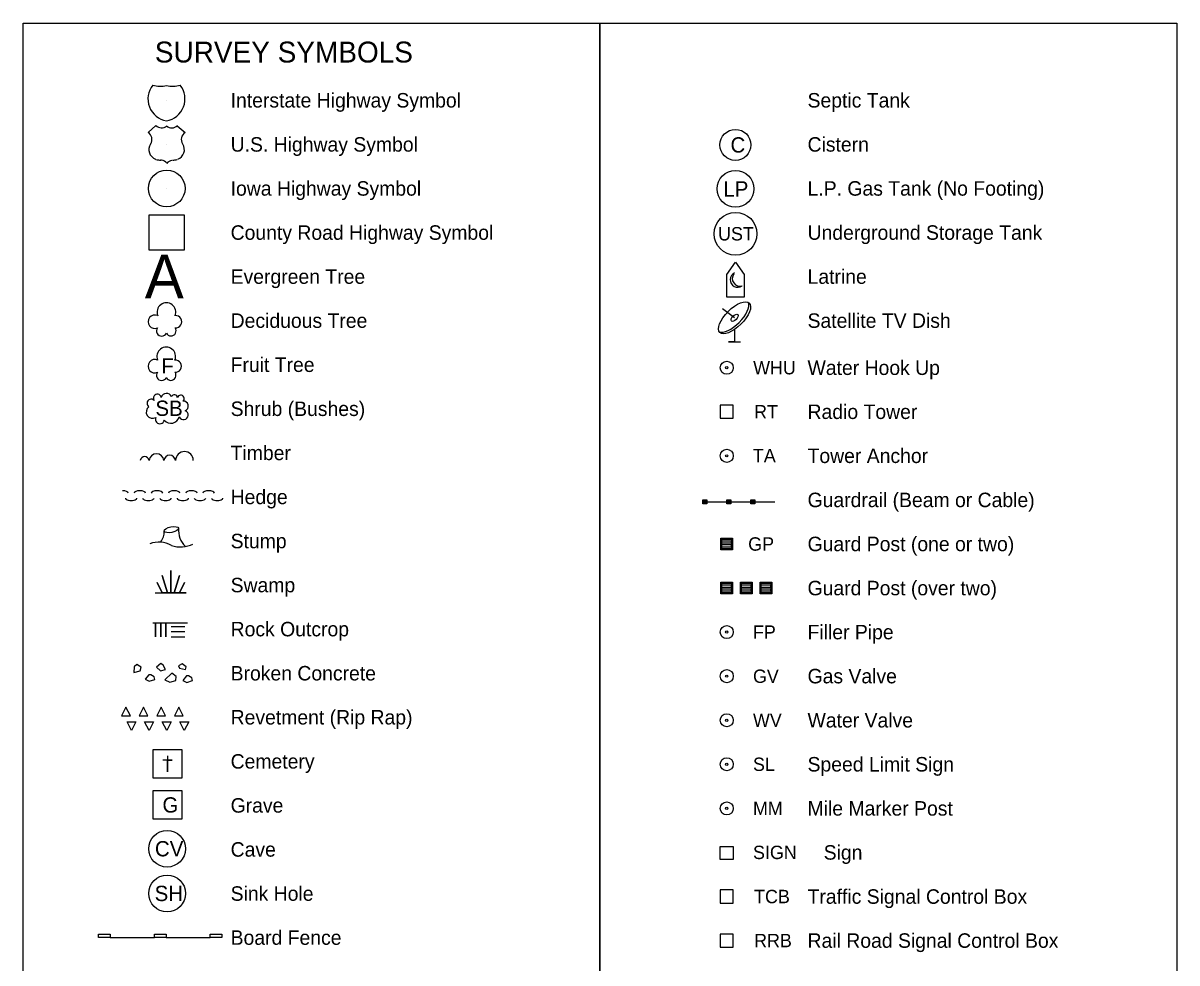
# Model space of a CAD drawing. Extents: x 6082259 to 6083454, y 5964102 to 5966092.
# Drawn here: x 6082259 to 6083454, y 5965119 to 5966092 of the extents above; entities that cross this region are included whole.
import ezdxf

# ---------------------------------------------------------------- set-up
doc = ezdxf.new("R2010")
doc.units = 0
for name, color, linetype in [('Default', 7, 'Continuous'), ('dsnTextShtTitle', 7, 'Continuous'), ('ShtPlotIdentification', 7, 'Continuous')]:
    doc.layers.add(name, color=color, linetype=linetype)

msp = doc.modelspace()

# ---------------------------------------------------------------- linework, layer by layer
at = {"layer": 'Default'}
for points in [[(6082259, 5966092.2), (6082856.5, 5966092.2), (6082856.5, 5964102.2), (6082259, 5964102.2)], [(6082856.5, 5966092.2), (6083454, 5966092.2), (6083454, 5964102.2), (6082856.5, 5964102.2)]]:
    msp.add_lwpolyline(points, close=True, dxfattribs=at)
at = {"layer": 'ShtPlotIdentification'}
for p, q in [((6082407.8, 5966012.2), (6082407.8, 5966012.2)), ((6082388.5, 5965978.8), (6082396.6, 5965986)), ((6082418.8, 5965985.9), (6082426.9, 5965978.7)), ((6082391, 5965966.7), (6082391.4, 5965967.3)), ((6082407.8, 5965966.5), (6082407.8, 5965966.5)), ((6082396.7, 5965951), (6082396, 5965951.3)), ((6082402.5, 5965950.1), (6082401.5, 5965950.1)), ((6082407.8, 5965920.9), (6082407.8, 5965920.9)), ((6082995.9, 5965786.9), (6082983.5, 5965796.2)), ((6082412.3, 5965467.3), (6082426.5, 5965467.3)), ((6082412.3, 5965462), (6082426.5, 5965462)), ((6082412.3, 5965456.6), (6082426.5, 5965456.6))]:
    msp.add_line(p, q, dxfattribs=at)
for points in [[(6082389.5, 5965893.5), (6082426, 5965893.5), (6082426, 5965857), (6082389.5, 5965857), (6082389.5, 5965893.5)], [(6082987.8, 5965808.3), (6082987.8, 5965831.8), (6082996.9, 5965844.5), (6083005.9, 5965831.8), (6083005.9, 5965808.3), (6082987.8, 5965808.3)], [(6082995.9, 5965774.5), (6082995.9, 5965762.1), (6082989.7, 5965762.1), (6083002.1, 5965762.1)], [(6082987.8, 5965682.8), (6082987.8, 5965682.8), (6082994.6, 5965682.8), (6082994.6, 5965696.4), (6082981, 5965696.4), (6082981, 5965682.8), (6082987.8, 5965682.8)], [(6082963.2, 5965594.3), (6082963.2, 5965598.4), (6082967.3, 5965598.4), (6082967.3, 5965594.3), (6082963.2, 5965594.3), (6082963.2, 5965595.7), (6082967.3, 5965595.7), (6082967.3, 5965597), (6082963.2, 5965597)], [(6082963.2, 5965596.4), (6083037.5, 5965596.4)], [(6082988, 5965594.3), (6082988, 5965598.4), (6082992.1, 5965598.4), (6082992.1, 5965594.3), (6082988, 5965594.3), (6082988, 5965595.7), (6082992.1, 5965595.7), (6082992.1, 5965597), (6082988, 5965597)], [(6083012.7, 5965594.3), (6083012.7, 5965598.4), (6083016.9, 5965598.4), (6083016.9, 5965594.3), (6083012.7, 5965594.3), (6083012.7, 5965595.7), (6083016.9, 5965595.7), (6083016.9, 5965597), (6083012.7, 5965597)], [(6082982.8, 5965547.7), (6082982.8, 5965557.6), (6082992.7, 5965557.6), (6082992.7, 5965547.7), (6082982.8, 5965547.7), (6082982.8, 5965549.7), (6082992.7, 5965549.7), (6082992.7, 5965551.7), (6082982.8, 5965551.7), (6082982.8, 5965553.7), (6082992.7, 5965553.7), (6082992.7, 5965555.6), (6082982.8, 5965555.6)], [(6082396, 5965502.1), (6082428.1, 5965502.1), (6082421, 5965502.1), (6082426.3, 5965512.8), (6082421, 5965502.1), (6082415.6, 5965502.1), (6082421, 5965520), (6082415.6, 5965502.1), (6082412.1, 5965502.1), (6082412.1, 5965525.3), (6082412.1, 5965502.1), (6082408.5, 5965502.1), (6082403.2, 5965520), (6082408.5, 5965502.1), (6082403.2, 5965502.1), (6082397.8, 5965512.8), (6082403.2, 5965502.1)], [(6082982.8, 5965502.1), (6082982.8, 5965512), (6082992.7, 5965512), (6082992.7, 5965502.1), (6082982.8, 5965502.1), (6082982.8, 5965504.1), (6082992.7, 5965504.1), (6082992.7, 5965506), (6082982.8, 5965506), (6082982.8, 5965508), (6082992.7, 5965508), (6082992.7, 5965510), (6082982.8, 5965510)], [(6083003.2, 5965502.1), (6083003.2, 5965512), (6083013.1, 5965512), (6083013.1, 5965502.1), (6083003.2, 5965502.1), (6083003.2, 5965504.1), (6083013.1, 5965504.1), (6083013.1, 5965506), (6083003.2, 5965506), (6083003.2, 5965508), (6083013.1, 5965508), (6083013.1, 5965510), (6083003.2, 5965510)], [(6083023.5, 5965502.1), (6083023.5, 5965512), (6083033.4, 5965512), (6083033.4, 5965502.1), (6083023.5, 5965502.1), (6083023.5, 5965504.1), (6083033.4, 5965504.1), (6083033.4, 5965506), (6083023.5, 5965506), (6083023.5, 5965508), (6083033.4, 5965508), (6083033.4, 5965510), (6083023.5, 5965510)], [(6082393.5, 5965470.9), (6082396.2, 5965470.9), (6082396.2, 5965456.6), (6082396.2, 5965470.9), (6082401.6, 5965470.9), (6082401.6, 5965456.6), (6082401.6, 5965470.9), (6082406.9, 5965470.9), (6082406.9, 5965456.6), (6082406.9, 5965470.9), (6082429.2, 5965470.9)], [(6082361, 5965374.6), (6082370.2, 5965374.6), (6082365.6, 5965383.8), (6082361, 5965374.6)], [(6082379.3, 5965374.6), (6082388.4, 5965374.6), (6082383.9, 5965383.8), (6082379.3, 5965374.6)], [(6082397.6, 5965374.6), (6082406.7, 5965374.6), (6082402.1, 5965383.8), (6082397.6, 5965374.6)], [(6082415.8, 5965374.6), (6082424.9, 5965374.6), (6082420.4, 5965383.8), (6082415.8, 5965374.6)], [(6082366.7, 5965368.6), (6082375.8, 5965368.6), (6082371.2, 5965359.5), (6082366.7, 5965368.6)], [(6082384.9, 5965368.6), (6082394.1, 5965368.6), (6082389.5, 5965359.5), (6082384.9, 5965368.6)], [(6082403.2, 5965368.6), (6082412.3, 5965368.6), (6082407.8, 5965359.5), (6082403.2, 5965368.6)], [(6082421.5, 5965368.6), (6082430.6, 5965368.6), (6082426, 5965359.5), (6082421.5, 5965368.6)], [(6082393.8, 5965310.2), (6082393.8, 5965339.7), (6082423.4, 5965339.7), (6082423.4, 5965310.2), (6082393.8, 5965310.2)], [(6082408.6, 5965333.3), (6082408.6, 5965316.6), (6082408.6, 5965328.9), (6082413.5, 5965328.9), (6082403.7, 5965328.9)], [(6082987.8, 5965180.8), (6082987.8, 5965180.8), (6082994.6, 5965180.8), (6082994.6, 5965194.3), (6082981, 5965194.3), (6082981, 5965180.8), (6082987.8, 5965180.8)], [(6082349.4, 5965145), (6082395, 5965145)], [(6082407.2, 5965145), (6082452.8, 5965145)], [(6082464.9, 5965145), (6082464.9, 5965145)], [(6082987.8, 5965135.1), (6082987.8, 5965135.1), (6082994.6, 5965135.1), (6082994.6, 5965148.7), (6082981, 5965148.7), (6082981, 5965135.1), (6082987.8, 5965135.1)]]:
    msp.add_lwpolyline(points, dxfattribs=at)
for points in [[(6082981.8, 5965546.7), (6082981.8, 5965558.6), (6082993.7, 5965558.6), (6082993.7, 5965546.7)], [(6082981.8, 5965501.1), (6082981.8, 5965513), (6082993.7, 5965513), (6082993.7, 5965501.1)], [(6083002.2, 5965501.1), (6083002.2, 5965513), (6083014.1, 5965513), (6083014.1, 5965501.1)], [(6083022.5, 5965501.1), (6083022.5, 5965513), (6083034.4, 5965513), (6083034.4, 5965501.1)], [(6082401.7, 5965429), (6082397.3, 5965424.9), (6082401.5, 5965421.3), (6082406.4, 5965422.8), (6082404.3, 5965427.2)], [(6082423.7, 5965428.6), (6082419.9, 5965426.3), (6082421.1, 5965424.2), (6082427.1, 5965422.6), (6082427.9, 5965425.5)], [(6082376.8, 5965427.8), (6082374.2, 5965425.4), (6082373.7, 5965419.7), (6082380.2, 5965421.3), (6082381.5, 5965424.9), (6082379.7, 5965426.2)], [(6082389.2, 5965417.2), (6082385.6, 5965412.5), (6082389.8, 5965410.4), (6082395.5, 5965412.3), (6082394.9, 5965415.1), (6082391.3, 5965417.2)], [(6082413.2, 5965419), (6082406, 5965411.8), (6082410.9, 5965409.4), (6082417.4, 5965411.3), (6082417.6, 5965415.4)], [(6082428.2, 5965416), (6082424.6, 5965411.4), (6082428.7, 5965409.3), (6082434.4, 5965411.1), (6082433.9, 5965413.9), (6082430.3, 5965416)], [(6082393.7, 5965267.5), (6082393.7, 5965297.2), (6082423.5, 5965297.2), (6082423.5, 5965267.5)], [(6082981, 5965225.7), (6082981, 5965239.2), (6082994.6, 5965239.2), (6082994.6, 5965225.7)], [(6082337.2, 5965145), (6082337.2, 5965148.4), (6082349.4, 5965148.4), (6082349.4, 5965145)], [(6082395, 5965145), (6082395, 5965148.4), (6082407.2, 5965148.4), (6082407.2, 5965145)], [(6082452.8, 5965145), (6082452.8, 5965148.4), (6082464.9, 5965148.4), (6082464.9, 5965145)]]:
    msp.add_lwpolyline(points, close=True, dxfattribs=at)
for centre, radius in [((6082996.8, 5965966), 16), ((6082407.8, 5965920.9), 19), ((6082996.9, 5965920.5), 19), ((6082996.9, 5965873.9), 22.2), ((6082987.8, 5965735.2), 6.79), ((6082987.8, 5965735.2), 1.13), ((6082987.8, 5965644), 6.79), ((6082987.8, 5965644), 1.13), ((6082987.8, 5965461.4), 6.79), ((6082987.8, 5965461.4), 1.13), ((6082987.8, 5965415.8), 6.79), ((6082987.8, 5965415.8), 1.13), ((6082987.8, 5965370.1), 6.79), ((6082987.8, 5965370.1), 1.13), ((6082987.8, 5965324.5), 6.79), ((6082987.8, 5965324.5), 1.13), ((6082987.8, 5965278.8), 6.79), ((6082987.8, 5965278.8), 1.13), ((6082408.2, 5965237), 19), ((6082408.2, 5965190.7), 19)]:
    msp.add_circle(centre, radius, dxfattribs=at)
for centre, radius, start, end in [((6082411.4, 5966013.6), 23, 141.2897, 260.377), ((6082401.1, 5966050), 23.3, 250.8344, 286.0898), ((6082414, 5966050), 23.3, 253.9102, 289.1613), ((6082403.7, 5966013.6), 23, 279.623, 38.7204), ((6082414, 5966050), 23.3, 289.1818, 289.185), ((6082384.1, 5965971.6), 8.46, 328.1178, 58.4185), ((6082402.4, 5965992.1), 8.46, 226.652, 308.6604), ((6082413, 5965992.1), 8.46, 230.5703, 313.348), ((6082431.3, 5965971.5), 8.46, 121.5815, 211.8822), ((6082399.6, 5965961), 10.3, 145.8972, 250.3585), ((6082415.8, 5965960.9), 10.3, 289.6415, 34.1028), ((6082403.5, 5965974.1), 24.1, 253.4797, 265.7777), ((6082402.1, 5965943), 7.07, 33.6844, 87.4407), ((6082413.9, 5965942.9), 7.07, 95.8567, 146.3156), ((6082411.9, 5965974.1), 24.1, 274.6642, 286.5203), ((6082999.3, 5965826.4), 7.87, 116.2289, 304.7925), ((6083001.5, 5965827.5), 7.91, 142.8907, 286.2253), ((6082407.5, 5965792.7), 9.75, 338.2051, 201.7949), ((6082395.5, 5965782.8), 6.97, 65.4824, 294.5175), ((6082417, 5965782.8), 6.36, 265.9982, 94.0018), ((6082402.6, 5965773.2), 5.31, 142.7501, 335.3223), ((6082412.2, 5965773.4), 5.3, 206.5242, 35.4033), ((6082407.3, 5965746.8), 9.75, 338.2051, 201.7949), ((6082395.4, 5965736.8), 6.97, 65.4824, 294.5175), ((6082416.8, 5965736.8), 6.36, 265.9982, 94.0018), ((6082402.5, 5965727.3), 5.31, 142.7501, 335.3223), ((6082412.1, 5965727.4), 5.3, 206.5242, 35.4033), ((6082398.1, 5965703.7), 4.12, 10.5948, 214.3611), ((6082407.6, 5965703.1), 5.57, 22.6036, 165.7836), ((6082415.7, 5965704.1), 3.15, 0.4605, 158.7839), ((6082422.3, 5965703.3), 3.57, 311.3936, 166.4114), ((6082393.2, 5965689.4), 6.62, 125.8289, 299.2848), ((6082391.7, 5965698.3), 4.32, 45.3455, 236.8073), ((6082425, 5965695.5), 5.15, 290.9039, 94.3687), ((6082400.8, 5965681.8), 4.68, 157.0258, 349.7602), ((6082412.2, 5965686.7), 8.99, 220.0183, 343.6977), ((6082425.2, 5965686.2), 4.79, 204.8294, 69.8871), ((6082397.2, 5965638.4), 7.66, 5.6097, 174.3903), ((6082410.9, 5965638.4), 6.15, 6.8184, 173.1816), ((6082426.2, 5965639.2), 9.15, 0, 180), ((6082385, 5965638.5), 4.63, 8.8069, 171.1931), ((6082388.6, 5965565.5), 16.7, 319.4836, 1.8241), ((6082444, 5965567.1), 24, 175.4776, 225.2691), ((6082400.1, 5965530.5), 24.2, 58.6739, 113.6979), ((6082422.1, 5965578.6), 29, 251.1942, 296.4339)]:
    msp.add_arc(centre, radius, start, end, dxfattribs=at)
for centre, major_axis, ratio in [((6082995.9, 5965786.9), (-15.3, -15.3), 0.428571), ((6082995.9, 5965786.9), (-3.28, -3.28), 0.5), ((6082412.7, 5965567.5), (-7.43, -1.49), 0.385758)]:
    msp.add_ellipse(centre, major_axis=major_axis, ratio=ratio, dxfattribs=at)
for centre, major_axis, ratio, start_param, end_param in [((6082994.1, 5965788.6), (-15.3, -15.3), 0.428571, 0.159141, 2.993624), ((6082362.1, 5965605.4), (5.94, 0), 0.4, 0, 1.570796), ((6082379.9, 5965605.4), (-5.94, 0), 0.4, 4.712389, 6.283185), ((6082379.9, 5965605.4), (5.94, 0), 0.4, 0, 1.570796), ((6082397.7, 5965605.4), (-5.94, 0), 0.4, 4.712389, 6.283185), ((6082397.7, 5965605.4), (5.94, 0), 0.4, 0, 1.570796), ((6082415.5, 5965605.4), (-5.94, 0), 0.4, 4.712389, 6.283185), ((6082415.5, 5965605.4), (5.94, 0), 0.4, 0, 1.570796), ((6082433.4, 5965605.4), (-5.94, 0), 0.4, 4.712389, 6.283185), ((6082433.4, 5965605.4), (5.94, 0), 0.4, 0, 1.570796), ((6082451.2, 5965605.4), (-5.94, 0), 0.4, 4.712389, 6.283185), ((6082451.2, 5965605.4), (5.94, 0), 0.4, 0, 1.570796), ((6082371, 5965600.1), (-5.94, 0), 0.4, 0, 3.141593), ((6082388.8, 5965600.1), (-5.94, 0), 0.4, 0, 3.141593), ((6082406.6, 5965600.1), (-5.94, 0), 0.4, 0, 3.141593), ((6082424.5, 5965600.1), (-5.94, 0), 0.4, 0, 3.141593), ((6082442.3, 5965600.1), (-5.94, 0), 0.4, 0, 3.141593), ((6082460.1, 5965600.1), (-5.94, 0), 0.4, 0, 3.141593)]:
    msp.add_ellipse(centre, major_axis=major_axis, ratio=ratio, start_param=start_param, end_param=end_param, dxfattribs=at)

# ---------------------------------------------------------------- texts
at = {"layer": 'dsnTextShtTitle'}
for s, height, p in [('SURVEY SYMBOLS', 21.667, (6082395.5, 5966051.3)), ('Interstate Highway Symbol', 15, (6082474, 5966004.7)), ('Septic Tank', 15, (6083071.5, 5966004.7)), ('U.S. Highway Symbol', 15, (6082474, 5965959)), ('Cistern', 15, (6083071.5, 5965959)), ('Iowa Highway Symbol', 15, (6082474, 5965913.4)), ('L.P. Gas Tank (No Footing)', 15, (6083071.5, 5965913.4)), ('County Road Highway Symbol', 15, (6082474, 5965867.7)), ('Underground Storage Tank', 15, (6083071.5, 5965867.7)), ('Evergreen Tree', 15, (6082474, 5965822.1)), ('Latrine', 15, (6083071.5, 5965822.1)), ('Deciduous Tree', 15, (6082474, 5965776.5)), ('Satellite TV Dish', 15, (6083071.5, 5965776.5)), ('Fruit Tree', 15, (6082474, 5965730.8)), ('Water Hook Up', 15, (6083071.5, 5965727.7)), ('Shrub (Bushes)', 15, (6082474, 5965685.2)), ('Radio Tower', 15, (6083071.5, 5965682.1)), ('Timber', 15, (6082474, 5965639.5)), ('Tower Anchor', 15, (6083071.5, 5965636.5)), ('Hedge', 15, (6082474, 5965593.9)), ('Guardrail (Beam or Cable)', 15, (6083071.5, 5965590.8)), ('Stump', 15, (6082474, 5965548.2)), ('Guard Post (one or two)', 15, (6083071.5, 5965545.2)), ('Swamp', 15, (6082474, 5965502.6)), ('Guard Post (over two)', 15, (6083071.5, 5965499.5)), ('Rock Outcrop', 15, (6082474, 5965457)), ('Filler Pipe', 15, (6083071.5, 5965453.9)), ('Broken Concrete', 15, (6082474, 5965411.3)), ('Gas Valve', 15, (6083071.5, 5965408.3)), ('Revetment (Rip Rap)', 15, (6082474, 5965365.7)), ('Water Valve', 15, (6083071.5, 5965362.6)), ('Cemetery', 15, (6082474, 5965320)), ('Speed Limit Sign', 15, (6083071.5, 5965317)), ('Grave', 15, (6082474, 5965274.4)), ('Mile Marker Post', 15, (6083071.5, 5965271.3)), ('Sink Hole', 15, (6082474, 5965183.1)), ('Traffic Signal Control Box', 15, (6083071.5, 5965180)), ('Board Fence', 15, (6082474, 5965137.5)), ('Rail Road Signal Control Box', 15, (6083071.5, 5965134.4))]:
    msp.add_text(s, height=height, dxfattribs=at).set_placement(p)
at = {"layer": 'ShtPlotIdentification'}
for s, height, p in [('C', 15.8, (6082991.7, 5965958.1)), ('LP', 15.85, (6082984.3, 5965912.5)), ('UST', 13.87, (6082978.8, 5965867)), ('A', 45.3, (6082385.1, 5965807)), ('F', 15.8, (6082402.3, 5965729.3)), ('WHU', 13.82, (6083015.2, 5965728.3)), ('SB', 15.85, (6082396.1, 5965685.3)), ('RT', 13.87, (6083016.1, 5965682.7)), ('TA', 13.93, (6083014.8, 5965637.2)), ('GP', 13.87, (6083010, 5965545.7)), ('FP', 13.82, (6083015, 5965454.5)), ('GV', 13.82, (6083015, 5965408.8)), ('WV', 13.82, (6083015, 5965363.2)), ('SL', 13.82, (6083015, 5965317.6)), ('G', 15.8, (6082403.4, 5965274.5)), ('MM', 13.82, (6083015, 5965271.9)), ('CV', 15.85, (6082395.6, 5965229.1)), ('Cave', 15, (6082474, 5965228.8)), ('SIGN', 13.87, (6083015, 5965226.3)), ('Sign', 15, (6083088.2, 5965225.7)), ('SH', 15.85, (6082395.3, 5965182.8)), ('TCB', 13.87, (6083016.1, 5965180.6)), ('RRB', 13.87, (6083016.1, 5965135))]:
    msp.add_text(s, height=height, dxfattribs=at).set_placement(p)

doc.saveas('drawing.dxf')
